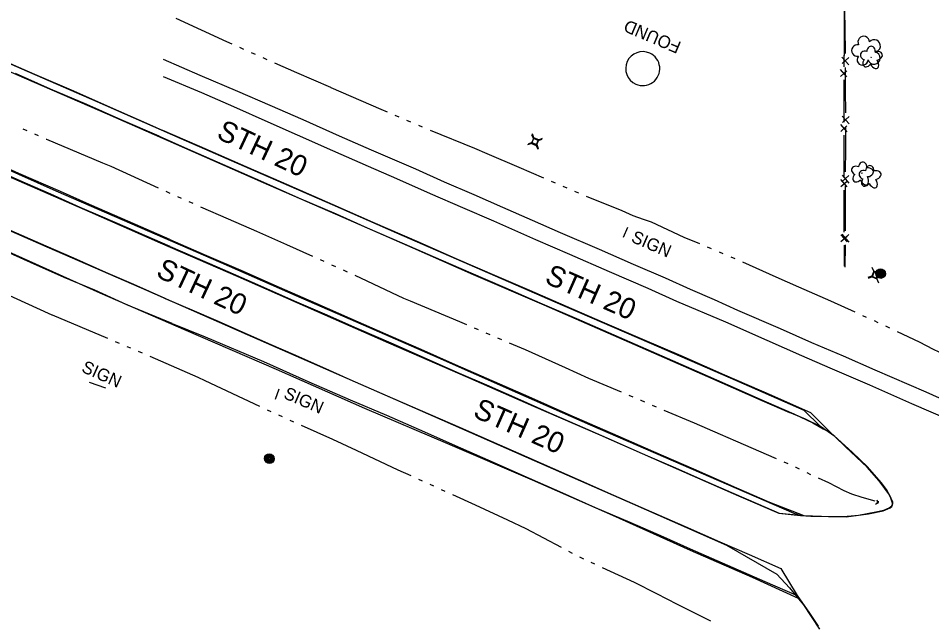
# Model space of a CAD drawing. Extents: x 588843 to 2552415, y 180129 to 269402.
# Drawn here: x 595442.4 to 595880.6, y 184644.9 to 184935.1 of the extents above; entities that cross this region are included whole.
import ezdxf

# ---------------------------------------------------------------- set-up
doc = ezdxf.new("R2010")
doc.units = 0
for name, color, linetype in [('Default', 7, 'Continuous'), ('E_DRN', 7, 'Continuous'), ('E_FEN_P', 7, 'Continuous'), ('E_LAND_Vegetation', 7, 'Continuous'), ('E_MISCPROP', 7, 'Continuous'), ('E_RDWY', 7, 'Continuous'), ('E_RDWY_Gravel', 7, 'Continuous'), ('E_RDWY_Text', 7, 'Continuous'), ('E_SGN', 7, 'Continuous'), ('E_SGN_Text', 7, 'Continuous'), ('E_UTL_AG_Bold', 7, 'Continuous'), ('E_WTR_P', 7, 'Continuous'), ('Level 12', 7, 'Continuous'), ('Level 15', 7, 'Continuous'), ('Level 18', 7, 'Continuous')]:
    doc.layers.add(name, color=color, linetype=linetype)

# ---------------------------------------------------------------- blocks, each defined once
blk = doc.blocks.new('SIGN')
at = {"layer": 'Default'}
blk.add_text('SIGN', height=12, dxfattribs=at).set_placement((-18.55, -6))
blk = doc.blocks.new('CULV2')
at = {"layer": 'E_DRN'}
blk.add_arc((20, 15), 24.6, 216.8699, 323.1301, dxfattribs=at)
blk = doc.blocks.new('POLE')
at = {"layer": 'Default'}
for radius in [4.46, 3.35, 2.23, 1.12]:
    blk.add_circle((0, 0), radius, dxfattribs=at)
blk = doc.blocks.new('PED')
at = {"layer": 'Default'}
for p, q in [((-2.5, 2.5), (-5.33, 5.33)), ((2.5, 2.5), (5.33, 5.33)), ((-2.5, -2.5), (-5.33, -5.33)), ((2.5, -2.5), (5.33, -5.33))]:
    blk.add_line(p, q, dxfattribs=at)
blk.add_lwpolyline([(-2.5, -2.5), (2.5, -2.5), (2.5, 2.5), (-2.5, 2.5)], close=True, dxfattribs=at)
blk = doc.blocks.new('DTRE')
at = {"layer": 'Default'}
blk.add_circle((-0.18, 0), 0.183, dxfattribs=at)
for centre, major_axis, ratio in [((-1.87, 5.32), (1.36, -4.98), 0.782863), ((-5.87, 0.15), (4.93, -0.12), 0.832022), ((4.06, 2.74), (-5.27, -2.93), 0.691916), ((-2.49, -5.24), (1.8, 4.86), 0.716896), ((3.54, -3.71), (-5.01, 4.58), 0.560249)]:
    blk.add_ellipse(centre, major_axis=major_axis, ratio=ratio, start_param=1.570796, end_param=4.712389, dxfattribs=at)
blk = doc.blocks.new('CULV2_4')
at = {"layer": 'E_DRN'}
blk.add_arc((65, 48), 80.7, 216.8699, 323.1301, dxfattribs=at)
blk = doc.blocks.new('PED_3')
at = {"layer": 'E_UTL_AG_Bold'}
for p, q in [((-8.2, 8.2), (-17.5, 17.5)), ((8.2, 8.2), (17.5, 17.5)), ((-8.2, -8.2), (-17.5, -17.5)), ((8.2, -8.2), (17.5, -17.5))]:
    blk.add_line(p, q, dxfattribs=at)
blk.add_lwpolyline([(-8.2, -8.2), (8.2, -8.2), (8.2, 8.2), (-8.2, 8.2)], close=True, dxfattribs=at)
blk = doc.blocks.new('POLE_3')
at = {"layer": 'E_MISCPROP'}
for radius in [14.6, 11, 7.32, 3.66]:
    blk.add_circle((0, 0), radius, dxfattribs=at)
blk = doc.blocks.new('DTRE_4')
at = {"layer": 'E_LAND_Vegetation'}
blk.add_circle((-0.6, 0), 0.601, dxfattribs=at)
for centre, major_axis, ratio in [((-6.1, 17.5), (4.5, -16.3), 0.782863), ((-19.3, 0.5), (16.2, -0.4), 0.832022), ((13.3, 9), (-17.3, -9.6), 0.691916), ((-8.2, -17.2), (5.9, 15.9), 0.716896), ((11.6, -12.2), (-16.4, 15), 0.560249)]:
    blk.add_ellipse(centre, major_axis=major_axis, ratio=ratio, start_param=1.570796, end_param=4.712389, dxfattribs=at)

msp = doc.modelspace()

# ---------------------------------------------------------------- linework, layer by layer
at = {"layer": 'E_FEN_P'}
for p, q in [((595837.48, 184916.4), (595840.78, 184912.64)), ((595840.76, 184916.24), (595837.56, 184913.39)), ((595839.91, 184907), (595836.84, 184910.51)), ((595836.85, 184907.15), (595839.84, 184909.8)), ((595837.61, 184888.06), (595840.91, 184884.31)), ((595840.9, 184887.9), (595837.7, 184885.05)), ((595839.96, 184880.55), (595836.89, 184884.07)), ((595836.89, 184880.71), (595839.89, 184883.36)), ((595837.59, 184859.73), (595840.86, 184855.95)), ((595840.87, 184859.55), (595837.64, 184856.72)), ((595840, 184854.11), (595836.93, 184857.62)), ((595836.94, 184854.27), (595839.93, 184856.92)), ((595840.05, 184827.67), (595836.98, 184831.18)), ((595836.98, 184827.83), (595839.98, 184830.48)), ((595837.48, 184831.39), (595840.75, 184827.61)), ((595840.76, 184831.21), (595837.54, 184828.39))]:
    msp.add_line(p, q, dxfattribs=at)
for points in [[(595838.77, 184939.71), (595838.88, 184928.89)], [(595838.88, 184928.89), (595838.98, 184919.84), (595838.98, 184918.07)], [(595838.49, 184911.69), (595838.48, 184917.3)], [(595839.02, 184911.37), (595839.07, 184900.55)], [(595838.52, 184895.34), (595838.5, 184905.44)], [(595839.07, 184900.55), (595839.12, 184889.73)], [(595838.53, 184885.25), (595838.52, 184895.34)], [(595839.15, 184883.03), (595839.17, 184880.19), (595839.14, 184872.21)], [(595838.56, 184868.9), (595838.54, 184879)], [(595839.14, 184872.21), (595839.11, 184861.39)], [(595838.58, 184858.81), (595838.56, 184868.9)], [(595839.08, 184854.69), (595839.05, 184843.87)], [(595838.61, 184842.46), (595838.59, 184852.56)], [(595838.62, 184832.37), (595838.61, 184842.46)], [(595839.05, 184843.87), (595839.04, 184840.12), (595839.01, 184833.05)], [(595838.65, 184816.02), (595838.64, 184826.12)], [(595838.98, 184826.36), (595838.93, 184815.54)]]:
    msp.add_lwpolyline(points, dxfattribs=at)
at = {"layer": 'E_RDWY'}
for points in [[(595134.71, 185046.12), (595164.34, 185033.17), (595195.78, 185019.45), (595229.67, 185004.53), (595267.39, 184987.93), (595302.67, 184972.52), (595340.61, 184955.96), (595378.48, 184939.52), (595411.56, 184925.03), (595444.19, 184910.78), (595480.11, 184895.09), (595520.48, 184877.33), (595555.93, 184861.77), (595593.06, 184845.64), (595623.82, 184832.01), (595658.68, 184816.92), (595699.72, 184798.98), (595744.81, 184779.39), (595783.86, 184762.42), (595819.21, 184746.89), (595827.17, 184739.02)], [(595106.31, 185004.68), (595129.16, 184994.7), (595160.49, 184980.91), (595189.64, 184968.14), (595214.41, 184957.31), (595245.99, 184943.35), (595279.17, 184928.83), (595308.55, 184915.79), (595338.88, 184902.49), (595371.94, 184887.91), (595409.8, 184871.47), (595442.79, 184857.01), (595476.7, 184842.19), (595510.49, 184827.3), (595547.69, 184811.05), (595585.53, 184794.51), (595619.96, 184779.34), (595657.89, 184762.78), (595689.51, 184748.91), (595721.33, 184735.08), (595752.47, 184721.35), (595787.82, 184705.81), (595807.15, 184697.54), (595817.69, 184696.33)], [(595433.32, 184915.63), (595450.21, 184908.16), (595468.93, 184900.2), (595490.54, 184890.66), (595505.42, 184884), (595511.74, 184881.14)], [(595511.88, 184907.16), (595530.33, 184899.38), (595545.66, 184892.66), (595562.22, 184885.39), (595576.27, 184879.05), (595593.2, 184871.6), (595610.28, 184863.99), (595623.79, 184858.15), (595640.03, 184850.99), (595655.44, 184844.24), (595670.31, 184837.76), (595690.49, 184828.91), (595706.9, 184821.75), (595725.78, 184813.48), (595744.44, 184805.43), (595758.12, 184799.34), (595781.6, 184789.34), (595801.47, 184780.52), (595818.09, 184773.18), (595831.7, 184767.31), (595850.64, 184759.05), (595870.92, 184750.15), (595890.48, 184741.65)], [(595515.23, 184825.48), (595537.88, 184815.73), (595557.26, 184807.24), (595574.79, 184799.48), (595590.43, 184792.71), (595604.9, 184786.25), (595622.25, 184778.74), (595639.55, 184771.09), (595653.9, 184764.75), (595666.94, 184759.04), (595681.89, 184752.48), (595695.86, 184746.29), (595710.48, 184739.95), (595727.31, 184732.59), (595743.16, 184725.55), (595757.61, 184719.21), (595770.6, 184713.52), (595784.56, 184707.47), (595797.47, 184701.78), (595807.44, 184697.43), (595819.19, 184696.36), (595827.68, 184696.03), (595838.31, 184695.83), (595845.41, 184696.52), (595853.75, 184698.08), (595857.54, 184698.87), (595860.19, 184700.13), (595861.35, 184700.99), (595861.85, 184701.83), (595860.92, 184704.64), (595859.14, 184708.41), (595856.43, 184712.12), (595849.81, 184719.74), (595842.41, 184726.73), (595835.3, 184733.19), (595832.12, 184736.02), (595822.6, 184745.65), (595803.8, 184754.02), (595781.32, 184763.72), (595760.41, 184772.97), (595740.95, 184781.32), (595722.73, 184789.14), (595705.39, 184796.76), (595687.78, 184804.38), (595673.23, 184810.68), (595652.48, 184819.6), (595634.91, 184827.43), (595612.71, 184837.05), (595593.41, 184845.46), (595568.7, 184856.44), (595551.83, 184863.76), (595529.56, 184873.58), (595511.74, 184881.14)], [(595515.23, 184825.48), (595503.17, 184830.81), (595493.74, 184834.97), (595482.96, 184839.66), (595472.18, 184844.3), (595458.14, 184850.58), (595445.97, 184855.93), (595431.33, 184862.31)], [(595408.34, 184846.29), (595456.13, 184825.33), (595503.94, 184804.47), (595552.17, 184783.28), (595594.84, 184764.58), (595641.54, 184744.13), (595689.91, 184722.7), (595736.87, 184702.07), (595782.19, 184682.21), (595806.34, 184668.22), (595812.31, 184661.73), (595819.04, 184653.49), (595826.65, 184641.82)], [(595512.97, 184800.58), (595497.86, 184807.32), (595484.44, 184813.09), (595469.14, 184819.96), (595455.75, 184825.71), (595438.99, 184832.99)], [(595512.97, 184800.58), (595526.85, 184794.62), (595537.17, 184790.1), (595552.65, 184783.19), (595563.62, 184778.42), (595575.43, 184773.26), (595588.3, 184767.61), (595601.5, 184761.71), (595621.96, 184752.72), (595640.03, 184744.86), (595654.31, 184738.55), (595669.26, 184732.01), (595686.3, 184724.52), (595710.95, 184713.61), (595727.98, 184706.13), (595743.67, 184699.18), (595762.32, 184691.1), (595778.92, 184683.71), (595793.04, 184677.58), (595808.18, 184670.95), (595815.99, 184657.9), (595822.01, 184649.56), (595826.01, 184643.28)], [(595817.69, 184696.33), (595822.64, 184696.07), (595839.46, 184695.68), (595850.23, 184697.18), (595857.3, 184698.59), (595860.69, 184700.1), (595861.48, 184700.7), (595861.79, 184701.43), (595861.85, 184702.75), (595860.27, 184706.27), (595855.4, 184713.07), (595849.54, 184719.63), (595839.12, 184729.32), (595834.03, 184734.23), (595827.17, 184739.02)]]:
    msp.add_lwpolyline(points, dxfattribs=at)
at = {"layer": 'E_RDWY_Gravel'}
for points in [[(595132.18, 185043.37), (595170.7, 185026.57), (595209.56, 185009.65), (595252.06, 184991.09), (595293.62, 184972.8), (595331.36, 184956.29), (595368.5, 184940.16), (595408.23, 184922.68), (595445.34, 184906.46), (595485.03, 184889.2), (595522.11, 184872.88), (595559.83, 184856.27), (595598.12, 184839.51), (595631.65, 184824.79), (595660.7, 184812.05), (595694.47, 184797.47), (595735.44, 184779.65), (595773.07, 184763.08), (595798.99, 184751.62), (595812.33, 184745.74)], [(595107.08, 185007.74), (595130.91, 184997.29), (595167.61, 184981.07), (595203.48, 184965.19), (595240.21, 184949.07), (595279.23, 184932), (595314.01, 184916.62), (595352.15, 184899.7), (595390.63, 184882.88), (595424.57, 184868.16), (595460.44, 184852.28), (595500.58, 184834.79), (595539.63, 184817.81), (595575.62, 184802), (595610.46, 184786.82), (595643.7, 184772.19), (595681.84, 184755.26), (595716.72, 184739.86), (595756.6, 184722.55), (595786.8, 184709.49), (595814.41, 184697.45)], [(595101.48, 184970.64), (595135.84, 184955.45), (595168.27, 184940.84), (595204.09, 184925.49), (595240.81, 184909.37), (595278.94, 184892.75), (595317.54, 184876), (595361.39, 184856.76), (595400.26, 184839.84), (595444.26, 184820.04), (595481.64, 184803.33), (595522.78, 184785.36), (595566.07, 184766.68), (595608.43, 184747.96), (595648.29, 184730.96), (595688.94, 184713.44), (595727.39, 184696.52), (595764.65, 184679.74), (595794.46, 184666.79), (595816.46, 184656.65)], [(595511.9, 184915.48), (595529.6, 184907.8), (595547.67, 184900.02), (595563.16, 184893.28), (595578.91, 184886.44), (595596.31, 184878.59), (595611.7, 184871.96), (595632.92, 184862.74), (595646.74, 184856.53), (595660.9, 184850.5), (595674.75, 184844.38), (595688.94, 184838.12), (595702.41, 184832.24), (595721.1, 184824.28), (595737.39, 184817.1), (595752.68, 184810.42), (595764.66, 184805.1), (595776.24, 184800.07), (595787.44, 184795.01), (595807.79, 184786.11), (595822.83, 184779.46), (595838.04, 184772.94), (595853.24, 184766.32), (595877.79, 184755.69), (595888.77, 184750.8)], [(595509.96, 184878.42), (595491.74, 184886.31), (595475.29, 184893.63), (595457.93, 184901.07), (595441.15, 184908.51)], [(595509.96, 184878.42), (595523.54, 184872.39), (595542.95, 184863.9), (595559.99, 184856.44), (595576.85, 184848.93), (595594.94, 184841.12), (595609.79, 184834.51), (595627.54, 184826.81), (595645.07, 184819.05), (595659.49, 184812.93), (595675.82, 184805.85), (595692.56, 184798.54), (595710.18, 184790.89), (595728.14, 184783.1), (595748.59, 184774.06), (595767.84, 184765.59), (595782.75, 184759.06), (595801.14, 184751.01), (595814.46, 184745.1), (595823.46, 184740.86), (595828.56, 184738.01), (595832.12, 184736.02)], [(595515.16, 184828.88), (595492.37, 184838.72), (595476.55, 184845.6), (595462.64, 184851.89), (595442.75, 184860.59), (595430.61, 184865.91)], [(595515.16, 184828.88), (595531.64, 184821.69), (595550.34, 184813.62), (595567.56, 184806.05), (595585.11, 184798.34), (595601.43, 184791.15), (595621.15, 184782.54), (595635.54, 184776.17), (595651.97, 184768.91), (595664.41, 184763.43), (595687.12, 184753.45), (595706.48, 184744.91), (595730.04, 184734.56), (595747.15, 184727.15), (595766.35, 184718.76), (595786.9, 184709.63), (595802.74, 184702.73), (595819.19, 184696.36)], [(595516.21, 184788.6), (595494.57, 184797.44), (595479.19, 184804.49), (595464.42, 184810.58), (595450.09, 184817.07), (595433.33, 184824.54)], [(595516.21, 184788.6), (595532.16, 184782.19), (595560.03, 184770.22), (595581.86, 184760.53), (595601.7, 184751.95), (595619.01, 184744.56), (595634.71, 184737.58), (595654.47, 184728.91), (595671.63, 184721.33), (595687.4, 184714.29), (595703.44, 184707.25), (595719.2, 184700.28), (595735.72, 184693.13), (595751.91, 184686.12), (595764.73, 184680.32), (595782.66, 184672.59), (595800.45, 184664.72), (595815.99, 184657.9)], [(595827.17, 184739.02), (595819.96, 184742.57), (595812.33, 184745.74)], [(595814.41, 184697.45), (595817.69, 184696.33)]]:
    msp.add_lwpolyline(points, dxfattribs=at)
at = {"layer": 'E_SGN'}
for points in [[(595734.66, 184834.56), (595732.54, 184829.81)], [(595476.5, 184760.45), (595484.34, 184757.6)], [(595565.77, 184752.27), (595567.54, 184757.14)]]:
    msp.add_lwpolyline(points, dxfattribs=at)
at = {"layer": 'E_WTR_P'}
for points in [[(595518.08, 184935.06), (595542.35, 184923.9), (595544.88, 184922.77)], [(595548.59, 184921.12), (595550.45, 184920.3)], [(595554.17, 184918.64), (595556.03, 184917.82)], [(595559.74, 184916.16), (595561.6, 184915.34)], [(595565.31, 184913.69), (595575.92, 184908.97), (595592.22, 184901.95), (595592.34, 184901.9)], [(595592.34, 184901.9), (595616.35, 184891.4), (595619.37, 184890.12)], [(595623.11, 184888.53), (595624.98, 184887.73)], [(595628.72, 184886.14), (595630.59, 184885.34)], [(595444.67, 184881.99), (595446.51, 184881.17)], [(595634.34, 184883.75), (595636.21, 184882.96)], [(595639.97, 184881.42), (595661.3, 184872.78), (595667.23, 184870.2)], [(595450.21, 184879.53), (595452.06, 184878.71)], [(595455.76, 184877.07), (595455.98, 184876.97), (595482.81, 184865.73)], [(595667.23, 184870.2), (595682.51, 184863.56), (595694.28, 184858.48)], [(595482.81, 184865.73), (595486.92, 184864.01), (595509.55, 184853.68)], [(595698.02, 184856.87), (595699.88, 184856.06)], [(595703.62, 184854.45), (595705.48, 184853.64)], [(595513.23, 184852), (595513.57, 184851.84), (595515.07, 184851.17)], [(595709.22, 184852.03), (595709.51, 184851.9), (595711.1, 184851.26)], [(595518.77, 184849.53), (595520.62, 184848.71)], [(595524.32, 184847.07), (595526.17, 184846.25)], [(595714.86, 184849.72), (595731.89, 184842.77), (595737.26, 184840.35), (595742.18, 184838.68)], [(595529.87, 184844.61), (595543.05, 184838.77), (595556.71, 184832.79)], [(595742.18, 184838.68), (595745.97, 184837.39), (595761.66, 184830.03), (595769.17, 184826.87)], [(595556.71, 184832.79), (595571.02, 184826.54), (595583.52, 184820.9)], [(595772.92, 184825.3), (595774.8, 184824.51)], [(595587.21, 184819.24), (595589.05, 184818.41)], [(595778.55, 184822.94), (595780.42, 184822.15)], [(595784.17, 184820.58), (595786.05, 184819.79)], [(595592.74, 184816.74), (595594.59, 184815.91)], [(595789.78, 184818.19), (595805.76, 184810.93), (595816.69, 184806.12)], [(595598.27, 184814.25), (595600.12, 184813.42)], [(595603.8, 184811.74), (595627.2, 184800.77), (595630.41, 184799.42)], [(595816.69, 184806.12), (595832.06, 184799.36), (595843.62, 184794.13)], [(595432.42, 184804.97), (595434.46, 184803.7), (595458.6, 184792.65)], [(595630.41, 184799.42), (595654.02, 184789.57), (595657.47, 184788.09)], [(595458.6, 184792.65), (595458.65, 184792.63), (595485.3, 184781.45)], [(595847.32, 184792.45), (595849.18, 184791.61)], [(595852.88, 184789.93), (595854.73, 184789.09)], [(595661.18, 184786.49), (595663.04, 184785.7)], [(595666.76, 184784.1), (595668.62, 184783.3)], [(595858.41, 184787.36), (595860.25, 184786.49)], [(595863.92, 184784.74), (595874.56, 184779.68), (595881.18, 184776.19), (595886.65, 184773.73), (595890.43, 184771.85)], [(595488.98, 184779.91), (595490.82, 184779.14)], [(595672.33, 184781.7), (595674.19, 184780.91)], [(595494.5, 184777.57), (595496.33, 184776.78)], [(595677.91, 184779.31), (595685.52, 184776.04), (595704.7, 184767.38)], [(595499.99, 184775.19), (595501.82, 184774.4)], [(595505.49, 184772.81), (595528.57, 184762.81), (595532, 184761.2)], [(595704.7, 184767.38), (595715.94, 184762.3), (595731.6, 184755.68)], [(595532, 184761.2), (595558.2, 184748.87)], [(595735.33, 184754.11), (595737.19, 184753.32)], [(595740.91, 184751.75), (595741.07, 184751.68), (595742.78, 184750.95)], [(595746.5, 184749.37), (595748.36, 184748.58)], [(595561.81, 184747.17), (595563.62, 184746.32)], [(595752.09, 184747), (595766.56, 184740.85), (595779.04, 184735.44)], [(595567.24, 184744.64), (595569.06, 184743.82)], [(595572.7, 184742.19), (595574.53, 184741.37)], [(595578.17, 184739.74), (595593.08, 184733.07), (595604.5, 184727.72)], [(595779.04, 184735.44), (595786.5, 184732.2), (595805.95, 184723.77)], [(595604.5, 184727.72), (595624.55, 184718.32), (595630.75, 184715.5)], [(595809.66, 184722.15), (595811.49, 184721.3)], [(595815.16, 184719.6), (595815.37, 184719.51), (595816.99, 184718.73)], [(595820.64, 184716.99), (595822.47, 184716.12)], [(595826.13, 184714.4), (595830.99, 184712.27), (595838.43, 184708.44), (595842.07, 184706.81), (595846.97, 184705.23), (595853.22, 184703.38)], [(595634.39, 184713.85), (595636.2, 184713.02)], [(595639.84, 184711.37), (595641.66, 184710.55)], [(595645.29, 184708.9), (595647.11, 184708.07)], [(595650.75, 184706.42), (595661.59, 184701.49), (595677.01, 184694.25)], [(595677.01, 184694.25), (595685.89, 184690.08), (595702.82, 184681.15)], [(595706.35, 184679.29), (595708.12, 184678.36)], [(595711.65, 184676.49), (595711.99, 184676.32), (595713.46, 184675.64)], [(595717.08, 184673.96), (595718.89, 184673.13)], [(595722.52, 184671.45), (595737.88, 184664.36), (595748.58, 184658.86)], [(595748.58, 184658.86), (595758.51, 184653.76), (595774.41, 184645.79)]]:
    msp.add_lwpolyline(points, dxfattribs=at)
at = {"layer": 'Level 12'}
for start, end in [(65.6332, 245.6332), (245.6332, 65.6332)]:
    msp.add_arc((595741.95, 184910.89), 8.17, start, end, dxfattribs=at)
at = {"layer": 'Level 15'}
for points in [[(595838.77, 184917.13), (595838.6, 184986.37)], [(595838.75, 184927.03), (595838.72, 184936.99)], [(595838.77, 184917.13), (595838.75, 184927.03)]]:
    msp.add_lwpolyline(points, dxfattribs=at)
at = {"layer": 'Level 18'}
for centre, radius, start, end in [((595847.93, 184923.63), 2.78, 1.3946, 209.1675), ((595852.97, 184921.77), 2.97, 278.4237, 139.6575), ((595844.93, 184919.55), 2.78, 78.0716, 279.0826), ((595847.39, 184915.15), 2.61, 140.7797, 358.7123), ((595852.86, 184915.91), 2.97, 196.0745, 79.0477)]:
    msp.add_arc(centre, radius, start, end, dxfattribs=at)

# ---------------------------------------------------------------- block references
at = {"layer": 'E_DRN'}
for name, p, xscale, yscale, rotation in [('CULV2_4', (595853.58, 184701.75), 0.0168980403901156, 0.016898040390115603, 69.1770681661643), ('CULV2', (595854.14, 184702.09), 0.037126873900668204, 0.03712687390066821, 55.79783216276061)]:
    msp.add_blockref(name, p, dxfattribs=dict(at, xscale=xscale, yscale=yscale, rotation=rotation))
at = {"layer": 'E_LAND_Vegetation'}
for name, p, xscale, yscale, rotation in [('DTRE_4', (595851.58, 184916.25), 0.15240030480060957, 0.15240030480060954, -16.435432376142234), ('DTRE', (595847.18, 184860.66), 0.5000000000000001, 0.4999999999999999, -23.4811063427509), ('DTRE_4', (595850.95, 184858.98), 0.15240030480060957, 0.15240030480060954, -16.435432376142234)]:
    msp.add_blockref(name, p, dxfattribs=dict(at, xscale=xscale, yscale=yscale, rotation=rotation))
at = {"layer": 'E_MISCPROP'}
for name, p, xscale, yscale, rotation in [('POLE', (595855.99, 184812.59), 0.5000000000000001, 0.4999999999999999, -23.4811063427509), ('POLE_3', (595856.14, 184812.44), 0.1524003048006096, 0.15240030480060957, 67.12813611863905), ('POLE_3', (595562.8, 184723.81), 0.1524003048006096, 0.15240030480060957, 67.12813611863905), ('POLE', (595562.95, 184723.59), 0.5, 0.5, -23.4412616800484)]:
    msp.add_blockref(name, p, dxfattribs=dict(at, xscale=xscale, yscale=yscale, rotation=rotation))
at = {"layer": 'E_SGN_Text'}
for p, xscale, yscale, rotation in [((595745.68, 184826.95), 0.5000000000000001, 0.4999999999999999, -23.4811063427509), ((595482.04, 184764.47), 0.49999999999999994, 0.49999999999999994, -24.085783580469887), ((595578.96, 184751.9), 0.5000000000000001, 0.4999999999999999, -23.4811063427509)]:
    msp.add_blockref('SIGN', p, dxfattribs=dict(at, xscale=xscale, yscale=yscale, rotation=rotation))
at = {"layer": 'E_UTL_AG_Bold'}
for name, p, xscale, yscale, rotation in [('PED_3', (595690.21, 184875.68), 0.1524003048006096, 0.15240030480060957, 67.12813611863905), ('PED', (595690.44, 184876.07), 0.5000000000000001, 0.4999999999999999, -23.4811063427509), ('PED', (595853.44, 184811.95), 0.5000000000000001, 0.4999999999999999, -23.4811063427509), ('PED_3', (595853.63, 184811.63), 0.1524003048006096, 0.15240030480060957, 67.12813611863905)]:
    msp.add_blockref(name, p, dxfattribs=dict(at, xscale=xscale, yscale=yscale, rotation=rotation))

# ---------------------------------------------------------------- texts
at = {"layer": 'E_RDWY_Text'}
for rotation, p in [(334.929, (595537.02, 184877.69)), (334.929, (595507.99, 184811.25)), (336.1647, (595694.41, 184808.22)), (336.1647, (595660.03, 184743.94))]:
    msp.add_text('STH 20', height=10, rotation=rotation, dxfattribs=at).set_placement(p)
at = {"layer": 'Level 12'}
msp.add_text('FOUND', height=6, rotation=157, dxfattribs=at).set_placement((595760.84, 184923.42))

doc.saveas('drawing.dxf')
